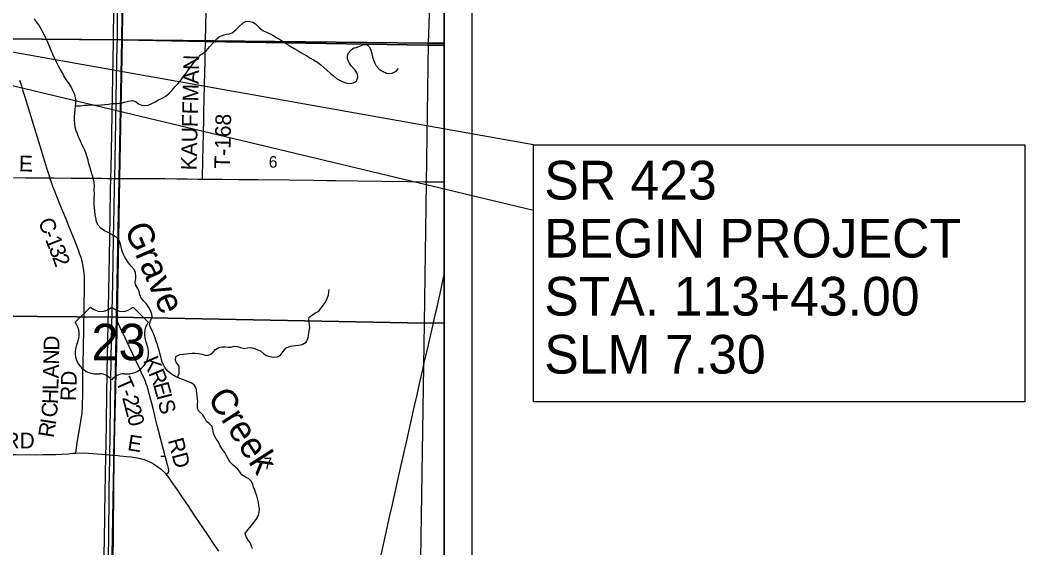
# Model space of a CAD drawing. Extents: x -9.1 to 34, y -3.1 to 22.
# Drawn here: x 7.865 to 11.501, y 15.91 to 17.82 of the extents above; entities that cross this region are included whole.
import ezdxf

# ---------------------------------------------------------------- set-up
doc = ezdxf.new("R2010")
doc.units = 0
for name, color, linetype in [('GM_X_County_Road', 7, 'Continuous'), ('GM_X_County_Road_Text', 7, 'Continuous'), ('GM_X_Minor_River', 7, 'Continuous'), ('GM_X_Minor_River_Text', 7, 'Continuous'), ('GM_X_Section', 7, 'Continuous'), ('GM_X_Section_Text', 7, 'Continuous'), ('GM_X_State_Route', 7, 'Continuous'), ('GM_X_Township', 7, 'Continuous'), ('GM_X_Township_Road', 7, 'Continuous'), ('GM_X_Township_Road_Text', 7, 'Continuous'), ('GM_X_US_Location', 7, 'Continuous'), ('GM_X_US_Route', 7, 'Continuous'), ('GM_X_US_Shield', 7, 'Continuous'), ('SH_Data', 7, 'Continuous'), ('SH_Text', 7, 'Continuous')]:
    doc.layers.add(name, color=color, linetype=linetype)

msp = doc.modelspace()

# ---------------------------------------------------------------- linework, layer by layer
at = {"layer": 'GM_X_County_Road'}
for points in [[(7.5906, 17.2523), (7.6358, 17.2517), (7.6699, 17.2515), (7.7072, 17.2509), (7.7694, 17.2501), (7.8315, 17.2497), (7.8844, 17.2494), (7.934, 17.2486), (7.9588, 17.2487), (7.9721, 17.2488)], [(8.0664, 16.2531), (8.0686, 16.2702), (8.0733, 16.2983), (8.0779, 16.3249), (8.0824, 16.3524), (8.0864, 16.3771), (8.088, 16.3894), (8.0891, 16.4018), (8.0902, 16.4173), (8.091, 16.4359), (8.0915, 16.4577), (8.0921, 16.5106), (8.0926, 16.5417), (8.0931, 16.5728), (8.0952, 16.7004), (8.0966, 16.7782), (8.098, 16.8591), (8.0981, 16.8777), (8.0977, 16.8933), (8.0971, 16.9025), (8.0962, 16.9118), (8.0949, 16.921), (8.0926, 16.9332), (8.0906, 16.9423), (8.0883, 16.9513), (8.0857, 16.9602), (8.0817, 16.972), (8.0763, 16.9865), (8.0614, 17.0241), (8.0463, 17.0617), (8.0313, 17.0993), (8.0093, 17.1541), (7.9921, 17.1975), (7.9839, 17.2177), (7.9781, 17.2322), (7.9721, 17.2488)], [(7.2729, 16.2483), (7.2946, 16.248), (7.3288, 16.2479), (7.3785, 16.2474), (7.4159, 16.2473), (7.4438, 16.2471), (7.4967, 16.2468), (7.5433, 16.2469), (7.5806, 16.2471), (7.6148, 16.2473), (7.6459, 16.2472), (7.6894, 16.2473), (7.7453, 16.2476), (7.7764, 16.2474), (7.8199, 16.2477), (7.851, 16.2477), (7.9224, 16.2469), (7.9473, 16.2474), (7.9655, 16.2476)], [(7.9655, 16.2476), (7.9663, 16.2476), (7.994, 16.2481), (8.0403, 16.2507), (8.056, 16.252), (8.0664, 16.2531)], [(8.0664, 16.2531), (8.0968, 16.2533), (8.1128, 16.2525), (8.16, 16.2491), (8.1754, 16.2477), (8.1799, 16.2472)], [(8.1799, 16.2472), (8.1896, 16.2464), (8.1979, 16.2456), (8.2067, 16.2448)], [(8.2067, 16.2448), (8.2187, 16.2437)], [(8.2187, 16.2437), (8.2257, 16.2431), (8.2504, 16.2407), (8.267, 16.239), (8.2811, 16.237), (8.2902, 16.2355), (8.2993, 16.2335), (8.3082, 16.2312), (8.3141, 16.2293), (8.3227, 16.2261), (8.3312, 16.2224), (8.3396, 16.2184), (8.3477, 16.2139), (8.3555, 16.209), (8.3631, 16.2037), (8.3704, 16.1981), (8.3751, 16.1941), (8.3842, 16.1857), (8.3888, 16.1814), (8.3939, 16.176)], [(8.4316, 16.1231), (8.4237, 16.1348), (8.4131, 16.1502), (8.404, 16.1628), (8.3939, 16.176)], [(8.5838, 15.8975), (8.565, 15.9259), (8.5441, 15.9569), (8.5285, 15.9802), (8.4954, 16.0292), (8.4727, 16.0627), (8.4482, 16.0988), (8.4316, 16.1231)]]:
    msp.add_lwpolyline(points, dxfattribs=at)
at = {"layer": 'GM_X_Minor_River'}
for points in [[(8.2332, 16.9877), (8.2306, 16.9994), (8.228, 17.0093), (8.2235, 17.0222), (8.2137, 17.0325), (8.2035, 17.0401), (8.1925, 17.0462), (8.1808, 17.0519), (8.1702, 17.0573), (8.1566, 17.0668), (8.146, 17.0786), (8.1415, 17.0903), (8.1385, 17.1036), (8.1371, 17.115), (8.1352, 17.1298), (8.1337, 17.14), (8.133, 17.1529), (8.1331, 17.1643), (8.1335, 17.1745), (8.1339, 17.1897), (8.1336, 17.206), (8.1337, 17.2192), (8.1326, 17.2314), (8.1307, 17.2424), (8.1277, 17.2538), (8.1247, 17.2636), (8.1217, 17.2735), (8.1169, 17.2891), (8.1142, 17.2997), (8.1109, 17.3122), (8.1071, 17.324), (8.1026, 17.3388), (8.0989, 17.349), (8.0933, 17.3608), (8.0876, 17.3729), (8.0812, 17.387), (8.0763, 17.3969), (8.0722, 17.4075), (8.0677, 17.4189), (8.064, 17.4318), (8.0625, 17.4443), (8.0614, 17.4568), (8.0614, 17.4689), (8.0626, 17.4829), (8.0638, 17.4962), (8.0654, 17.5083), (8.0662, 17.5193), (8.0666, 17.5307), (8.0644, 17.5455), (8.0606, 17.5554), (8.055, 17.5667), (8.0497, 17.5785), (8.0426, 17.5903), (8.0335, 17.6025), (8.0237, 17.6184), (8.0181, 17.6283), (8.0102, 17.6423), (8.0041, 17.6534), (7.997, 17.6674), (7.9902, 17.68), (7.9834, 17.6948), (7.9801, 17.705), (7.9752, 17.7156), (7.9639, 17.7422), (7.9583, 17.7536), (7.9519, 17.7669), (7.9462, 17.7779), (7.9387, 17.792), (7.9323, 17.8022), (7.9247, 17.8136), (7.9168, 17.8246)], [(8.0655, 17.5095), (8.0836, 17.5098), (8.0965, 17.512), (8.1071, 17.5123), (8.1204, 17.5131), (8.131, 17.5126), (8.1438, 17.5122), (8.1586, 17.5125), (8.1852, 17.5151), (8.1966, 17.5177), (8.2068, 17.518), (8.2174, 17.5176), (8.2303, 17.5191), (8.2432, 17.5225), (8.2572, 17.5262), (8.2713, 17.5284), (8.283, 17.5246), (8.2936, 17.5166), (8.3053, 17.5112), (8.3163, 17.5104), (8.3284, 17.5115), (8.3421, 17.5175), (8.3539, 17.5243), (8.3664, 17.5315), (8.379, 17.5371), (8.3919, 17.5446), (8.4025, 17.5529), (8.4147, 17.5665), (8.4265, 17.5794), (8.4364, 17.5907), (8.4474, 17.6036), (8.4554, 17.6141), (8.4665, 17.627), (8.4749, 17.6398), (8.4836, 17.6523), (8.4958, 17.669), (8.5065, 17.6818), (8.5175, 17.6939), (8.5282, 17.7014), (8.5396, 17.7097), (8.5498, 17.7226), (8.5635, 17.7373), (8.5769, 17.7513), (8.5867, 17.7603), (8.5993, 17.7656), (8.6122, 17.769), (8.622, 17.7701), (8.633, 17.7738), (8.6467, 17.7855), (8.6593, 17.798), (8.6726, 17.8093), (8.6836, 17.8153), (8.6969, 17.8145), (8.7071, 17.8126), (8.7173, 17.8057), (8.7305, 17.7928), (8.743, 17.7814), (8.7589, 17.7752), (8.7725, 17.7687), (8.7835, 17.763), (8.7967, 17.7546), (8.8069, 17.7478), (8.8202, 17.739), (8.8311, 17.7325), (8.8428, 17.7249), (8.8565, 17.7169), (8.8674, 17.7104), (8.878, 17.7039), (8.889, 17.6971), (8.9022, 17.6898), (8.9136, 17.6833), (8.9264, 17.6761), (8.9412, 17.6669), (8.9537, 17.6578), (8.9646, 17.6483), (8.9752, 17.6387), (8.9888, 17.6266), (8.999, 17.6178), (9.01, 17.6079), (9.0255, 17.5995), (9.0368, 17.5949), (9.0474, 17.5915), (9.0592, 17.5899), (9.0717, 17.5925), (9.0819, 17.5982), (9.0869, 17.6133), (9.0854, 17.6251), (9.0779, 17.6387), (9.0636, 17.6543), (9.0541, 17.6676), (9.05, 17.6794), (9.0497, 17.6904), (9.0539, 17.7006), (9.0627, 17.7123), (9.0725, 17.7191), (9.082, 17.721), (9.0972, 17.7262), (9.1078, 17.7307), (9.1196, 17.7307), (9.1294, 17.7212), (9.1343, 17.7105)], [(9.1343, 17.7105), (9.1376, 17.6973), (9.1403, 17.6863), (9.1433, 17.676), (9.1489, 17.6635), (9.1538, 17.654), (9.1647, 17.6418), (9.1749, 17.6346), (9.1905, 17.6281), (9.2007, 17.6265), (9.2113, 17.6276), (9.2261, 17.6348), (9.2349, 17.6446)], [(8.7063, 15.9061), (8.7029, 15.9156), (8.6984, 15.9266), (8.692, 15.9365), (8.683, 15.9494), (8.68, 15.9623), (8.6895, 15.9755), (8.7021, 15.9903), (8.7105, 16.0016), (8.7185, 16.0118), (8.7253, 16.0224), (8.7295, 16.0334), (8.7311, 16.0501), (8.7293, 16.0641), (8.7278, 16.0739), (8.7252, 16.0842), (8.7211, 16.0978), (8.7181, 16.1077), (8.7147, 16.1187), (8.7098, 16.1297), (8.7068, 16.1396), (8.7027, 16.1502), (8.6929, 16.1601), (8.6804, 16.1654), (8.6672, 16.1746), (8.6604, 16.1845), (8.6528, 16.1947), (8.6373, 16.2081), (8.6241, 16.2217), (8.6185, 16.2316), (8.6117, 16.2434), (8.6061, 16.2544), (8.5978, 16.2654), (8.5895, 16.2791), (8.5812, 16.2943), (8.574, 16.3049), (8.5684, 16.3148), (8.565, 16.3251), (8.562, 16.3376), (8.5587, 16.3497), (8.5492, 16.36), (8.539, 16.3676), (8.5338, 16.3797), (8.5259, 16.3911), (8.5119, 16.4041), (8.507, 16.4143), (8.5074, 16.4287), (8.5086, 16.4393), (8.5071, 16.4496), (8.5053, 16.4591), (8.5049, 16.4701), (8.5027, 16.4875), (8.4944, 16.5004), (8.4838, 16.5069), (8.4687, 16.5134), (8.4558, 16.5184), (8.443, 16.523), (8.4271, 16.5295), (8.4123, 16.5386), (8.3991, 16.5497), (8.3882, 16.5626), (8.3825, 16.5747), (8.378, 16.5854), (8.3743, 16.6024), (8.3709, 16.6142), (8.3679, 16.6252), (8.3649, 16.6354), (8.3619, 16.6453), (8.3574, 16.6571), (8.3533, 16.67), (8.3484, 16.6825), (8.3424, 16.6962), (8.3357, 16.7098), (8.333, 16.7193), (8.3373, 16.7314), (8.343, 16.7454), (8.3419, 16.7561), (8.3374, 16.7686), (8.331, 16.7796), (8.3219, 16.7933), (8.3121, 16.8032), (8.3019, 16.8161), (8.2986, 16.8256), (8.2963, 16.837), (8.2915, 16.8483), (8.2832, 16.862), (8.2817, 16.8738), (8.2833, 16.8836), (8.284, 16.8942), (8.2822, 16.9067), (8.2777, 16.9174), (8.2675, 16.9292), (8.2577, 16.9417), (8.2505, 16.9516), (8.243, 16.9641), (8.2385, 16.974), (8.2332, 16.9877)], [(8.4346, 16.5264), (8.4404, 16.5408), (8.4412, 16.5541), (8.4401, 16.5669), (8.4307, 16.5799), (8.4269, 16.5894), (8.4285, 16.6019), (8.4425, 16.609), (8.4551, 16.6109), (8.477, 16.613), (8.4869, 16.6141), (8.4983, 16.6141), (8.5115, 16.6133), (8.5244, 16.6106), (8.5388, 16.606), (8.5525, 16.6094), (8.5631, 16.6184), (8.5726, 16.6271), (8.5844, 16.6346), (8.5965, 16.6369), (8.606, 16.6372), (8.6178, 16.6364), (8.6284, 16.6364), (8.6394, 16.6397), (8.6515, 16.6386), (8.6629, 16.6343), (8.6769, 16.6316), (8.6882, 16.6339), (8.6989, 16.635), (8.7106, 16.6327), (8.7208, 16.6288), (8.736, 16.6219), (8.7473, 16.6124), (8.7571, 16.6056), (8.7692, 16.6021), (8.7833, 16.5998), (8.7961, 16.6009), (8.8056, 16.6065), (8.8175, 16.6205), (8.8262, 16.633), (8.8418, 16.6398), (8.8513, 16.6412), (8.8611, 16.6427), (8.874, 16.6438), (8.8858, 16.646), (8.9002, 16.6536), (8.9071, 16.6698), (8.909, 16.6801), (8.9114, 16.6937), (8.9133, 16.7062), (8.9122, 16.7164), (8.9104, 16.735), (8.9112, 16.7445), (8.9241, 16.7547), (8.9336, 16.7599), (8.9457, 16.7663), (8.9633, 16.789), (8.9701, 16.7988), (8.9762, 16.8125), (8.9805, 16.825), (8.9828, 16.8356), (8.9836, 16.845)]]:
    msp.add_lwpolyline(points, dxfattribs=at)
at = {"layer": 'GM_X_Section'}
for p, q in [((9.4, 17.736), (9.4, 18.7507)), ((9.4, 16.7243), (9.4, 17.736)), ((9.4, 15.7158), (9.4, 16.7243))]:
    msp.add_line(p, q, dxfattribs=at)
for points in [[(7.2285, 18.7534), (8.2465, 18.7547), (8.2334, 17.7485), (7.2227, 17.7567)], [(9.3766, 18.7507), (9.3419, 17.736), (8.2334, 17.7485), (8.2465, 18.7547)], [(8.2334, 17.7485), (8.2139, 16.745), (7.2066, 16.7532), (7.2227, 17.7567)], [(9.3419, 17.736), (9.3273, 16.7234), (8.2139, 16.745), (8.2334, 17.7485)], [(7.2066, 16.7532), (8.2139, 16.745), (8.1957, 15.7506), (7.6939, 15.7344), (7.1977, 15.7504)], [(8.2139, 16.745), (9.3273, 16.7234), (9.3112, 15.7153), (8.1958, 15.7211), (8.1957, 15.7506)]]:
    msp.add_lwpolyline(points, close=True, dxfattribs=at)
for points in [[(9.4, 18.7507), (9.3766, 18.7507), (9.3419, 17.736), (9.4, 17.736)], [(9.4, 17.736), (9.3419, 17.736), (9.3273, 16.7234), (9.4, 16.7243)], [(9.4, 16.7243), (9.3273, 16.7234), (9.3112, 15.7153), (9.4, 15.7158)]]:
    msp.add_lwpolyline(points, dxfattribs=at)
at = {"layer": 'GM_X_State_Route'}
for points in [[(7.8634, 17.6024), (7.8698, 17.5817), (7.8742, 17.5669), (7.8795, 17.5491), (7.8841, 17.5343), (7.8942, 17.5017), (7.9169, 17.4275), (7.9358, 17.3651), (7.9496, 17.3206), (7.9607, 17.285), (7.9721, 17.2488)], [(7.9721, 17.2488), (7.9884, 17.2487), (8.0496, 17.2477), (8.1309, 17.2473)], [(8.1309, 17.2473), (8.1614, 17.2472), (8.1819, 17.2469)], [(8.1819, 17.2469), (8.1863, 17.2469), (8.1879, 17.2469)], [(8.1879, 17.2469), (8.1934, 17.2469), (8.2049, 17.2469), (8.2074, 17.2469), (8.2239, 17.2469), (8.2266, 17.247), (8.2608, 17.2465), (8.3198, 17.2464), (8.3482, 17.2464)], [(8.3482, 17.2464), (8.3882, 17.2463), (8.4317, 17.2456), (8.469, 17.245), (8.5093, 17.2445), (8.5246, 17.2443), (8.5963, 17.2434), (8.6554, 17.2431), (8.6926, 17.2426), (8.7268, 17.2425), (8.8387, 17.241), (8.9256, 17.2401), (8.9754, 17.2393), (9.0064, 17.2388), (9.0872, 17.2379), (9.1742, 17.2366), (9.2674, 17.2353), (9.3295, 17.2348), (9.3668, 17.2343), (9.4, 17.2341)], [(9.1609, 15.8359), (9.1777, 15.9117), (9.1871, 15.9543), (9.2032, 16.027), (9.2121, 16.0664), (9.2331, 16.1606), (9.244, 16.2089), (9.2535, 16.2515), (9.2619, 16.2881), (9.2787, 16.363), (9.2925, 16.4243), (9.3017, 16.4638), (9.3106, 16.5031), (9.3222, 16.5547), (9.329, 16.585), (9.3389, 16.6274), (9.3477, 16.6668), (9.3595, 16.7184), (9.3684, 16.7577), (9.3739, 16.7811), (9.3788, 16.8033), (9.3849, 16.8306), (9.3963, 16.8822), (9.4, 16.8981)]]:
    msp.add_lwpolyline(points, dxfattribs=at)
at = {"layer": 'GM_X_Township'}
for points in [[(8.2717, 20.9), (8.2689, 20.7443), (8.2697, 20.6456), (8.2583, 19.8928), (8.2535, 19.4485), (8.2445, 18.5434), (8.2345, 17.7477), (8.5348, 17.7425), (9.3398, 17.7284), (9.4, 17.7292)], [(9.4, 17.7292), (9.4, 20.9), (8.2717, 20.9)], [(8.1877, 14.1), (8.1894, 14.7043), (8.1946, 15.2275), (8.1995, 15.7138), (8.204, 16.2447), (8.216, 16.7397), (8.2253, 17.2473), (8.2345, 17.7477), (8.2105, 17.7473), (7.8204, 17.7504), (7.686, 17.7514)], [(9.4, 17.7292), (9.3398, 17.7284), (8.5348, 17.7425), (8.2345, 17.7477), (8.2253, 17.2473), (8.216, 16.7397), (8.204, 16.2447), (8.1995, 15.7138), (8.1946, 15.2275), (8.1894, 14.7043), (8.1877, 14.1)], [(8.1877, 14.1), (9.4, 14.1), (9.4, 17.7292)]]:
    msp.add_lwpolyline(points, dxfattribs=at)
at = {"layer": 'GM_X_Township_Road'}
for points in [[(8.536, 17.7468), (8.5379, 17.8502), (8.5398, 17.931), (8.5409, 17.99), (8.5418, 18.0304), (8.5424, 18.0739), (8.5429, 18.1143), (8.5442, 18.187), (8.5451, 18.2375), (8.5452, 18.2542), (8.5457, 18.2741), (8.546, 18.2835), (8.5462, 18.292), (8.5464, 18.2978), (8.5466, 18.3052), (8.5468, 18.3128), (8.5469, 18.321), (8.5472, 18.3325), (8.5474, 18.3486), (8.5476, 18.3534), (8.5477, 18.3572), (8.5481, 18.3641), (8.5485, 18.3699)], [(8.5341, 17.6495), (8.5342, 17.6514), (8.5353, 17.7073), (8.5359, 17.7384), (8.536, 17.7468)], [(8.5246, 17.2443), (8.5247, 17.2503), (8.5262, 17.3127), (8.5282, 17.4093), (8.5294, 17.4592), (8.53, 17.4873), (8.531, 17.5341), (8.5322, 17.584), (8.5336, 17.632), (8.5341, 17.6495)], [(8.3905, 16.2412), (8.388, 16.2508), (8.3747, 16.302), (8.3661, 16.3351), (8.3616, 16.3532), (8.3555, 16.3773), (8.3485, 16.4044), (8.34, 16.4376), (8.3322, 16.4677), (8.3281, 16.4827), (8.3246, 16.4946), (8.3216, 16.5035), (8.3183, 16.5122), (8.3134, 16.5236), (8.307, 16.5378), (8.2979, 16.5576), (8.2849, 16.5856), (8.2592, 16.6391), (8.2449, 16.67), (8.2261, 16.7095), (8.217, 16.7293)], [(8.3737, 16.2412), (8.3867, 16.2412), (8.3905, 16.2412)], [(8.3939, 16.176), (8.4007, 16.1818), (8.4016, 16.183), (8.4023, 16.1844), (8.4031, 16.1874), (8.4033, 16.1905), (8.4029, 16.1936), (8.4021, 16.1966), (8.4004, 16.2026), (8.3999, 16.2056), (8.395, 16.2237), (8.3905, 16.2412)]]:
    msp.add_lwpolyline(points, dxfattribs=at)
at = {"layer": 'GM_X_US_Route'}
for points in [[(8.2072, 17.2359), (8.2074, 17.2469), (8.2085, 17.3114), (8.2114, 17.4543), (8.2143, 17.6096), (8.2166, 17.7277), (8.217, 17.7511), (8.2176, 17.8023), (8.2192, 17.939)], [(8.1663, 15.6793), (8.1707, 15.9589), (8.1712, 16.0042), (8.1716, 16.0352), (8.1723, 16.1081), (8.1736, 16.1733), (8.1754, 16.2477), (8.1761, 16.2789), (8.1805, 16.5492), (8.1835, 16.717), (8.1858, 16.8382), (8.1892, 17.0308), (8.191, 17.1147), (8.1925, 17.2047), (8.1934, 17.2469), (8.1943, 17.2824), (8.1965, 17.4098), (8.199, 17.5465), (8.2027, 17.7422), (8.2028, 17.7513), (8.204, 17.8603)], [(8.1702, 14.1), (8.1702, 14.1577), (8.1714, 14.4374), (8.1719, 14.6176), (8.1731, 14.8289), (8.1752, 15.0526), (8.1767, 15.2307), (8.177, 15.267), (8.1793, 15.4745), (8.1799, 15.5311), (8.1856, 15.9568), (8.1871, 16.0997), (8.1876, 16.1265), (8.1895, 16.2302), (8.1896, 16.2464), (8.1909, 16.3141), (8.1927, 16.4415), (8.1961, 16.6621), (8.2, 16.8672), (8.2034, 17.0318), (8.2052, 17.1374), (8.2068, 17.2151), (8.2072, 17.2359)]]:
    msp.add_lwpolyline(points, dxfattribs=at)
at = {"layer": 'GM_X_US_Shield'}
for p, q in [((8.1198, 16.7811), (8.0648, 16.7262)), ((8.3285, 16.7262), (8.2736, 16.7811)), ((8.1417, 16.5394), (8.1527, 16.5394)), ((8.2406, 16.5394), (8.2516, 16.5394))]:
    msp.add_line(p, q, dxfattribs=at)
for centre, radius, start, end in [((8.1582, 16.8204), 0.0549, 225.573, 314.427), ((8.2351, 16.8204), 0.0549, 225.573, 314.427), ((8.0018, 16.6821), 0.0769, 334.5471, 35.0009), ((8.3915, 16.6821), 0.0769, 144.9991, 205.4529), ((8.1409, 16.6163), 0.0769, 154.8319, 270.6383), ((8.2525, 16.6163), 0.0769, 269.3617, 25.1681), ((8.1527, 16.4845), 0.0549, 36.8699, 90), ((8.2406, 16.4845), 0.0549, 90, 143.1301)]:
    msp.add_arc(centre, radius, start, end, dxfattribs=at)
at = {"layer": 'SH_Data'}
for p, q in [((9.5, 21), (9.5, 14)), ((9.4, 20.9), (9.4, 14.1))]:
    msp.add_line(p, q, dxfattribs=at)
at = {"layer": 'SH_Text'}
for points in [[(9.7227, 17.3677), (5.8733, 18.0531), (9.7227, 17.1316)], [(9.7227, 17.3677), (11.5012, 17.3677), (11.5012, 16.4383), (9.7227, 16.4383)]]:
    msp.add_lwpolyline(points, close=True, dxfattribs=at)

# ---------------------------------------------------------------- texts
at = {"layer": 'GM_X_County_Road_Text'}
for s, height, rotation, p in [('E', 0.0568, 358.8923, (7.8601, 17.2724)), ('C', 0.0568, 291.6246, (7.9291, 17.0912)), ('-', 0.0568, 291.6159, (7.9463, 17.0478)), ('1', 0.0568, 291.5714, (7.9549, 17.0261)), ('3', 0.0568, 291.41, (7.9677, 16.9936)), ('2', 0.0568, 290.0694, (7.9804, 16.9614)), ('D', 0.0568, 88.7723, (8.0065, 16.6227)), ('N', 0.0568, 88.7723, (8.0054, 16.5727)), ('A', 0.0568, 88.7723, (8.0043, 16.5228)), ('RD', 0.05682, 88.5116, (8.0676, 16.4405)), ('L', 0.0568, 88.7791, (8.0034, 16.4803)), ('H', 0.0568, 87.9339, (8.0016, 16.4294)), ('C', 0.0568, 85.5794, (7.9978, 16.3803)), ('I', 0.0568, 80.8824, (7.9935, 16.3522)), ('RD', 0.05682, 0, (7.8083, 16.2699)), ('R', 0.0568, 80.6461, (7.9859, 16.3059)), ('E', 0.0568, 350.9456, (8.251, 16.2639))]:
    msp.add_text(s, height=height, rotation=rotation, dxfattribs=at).set_placement(p)
at = {"layer": 'GM_X_Minor_River_Text'}
for s, height, rotation, p in [('Grave', 0.09471, 293.3298, (8.2409, 17.0647)), ('Creek', 0.0947, 302.8291, (8.5404, 16.4525))]:
    msp.add_text(s, height=height, rotation=rotation, dxfattribs=at).set_placement(p)
at = {"layer": 'GM_X_Section_Text'}
for s, p in [('6', (8.765, 17.2856)), ('7', (8.7458, 16.194))]:
    msp.add_text(s, height=0.0419, rotation=0, dxfattribs=at).set_placement(p)
at = {"layer": 'GM_X_Township_Road_Text'}
for s, height, rotation, p in [('KAUFFMAN', 0.05682, 88.6577, (8.5035, 17.2755)), ('T-168', 0.05682, 88.5994, (8.6244, 17.2814)), ('K', 0.0568, 293.6965, (8.3088, 16.5883)), ('R', 0.0568, 292.2305, (8.3287, 16.5428)), ('T', 0.0568, 293.5931, (8.2098, 16.5126)), ('E', 0.0568, 285.5322, (8.3458, 16.5013)), ('-', 0.0568, 289.2175, (8.2264, 16.4748)), ('2', 0.0568, 284.7595, (8.2338, 16.4538)), ('I', 0.0568, 284.6705, (8.3572, 16.4606)), ('S', 0.0568, 284.6263, (8.3631, 16.438)), ('2', 0.0568, 284.555, (8.2427, 16.42)), ('0', 0.0568, 284.5184, (8.2515, 16.3862)), ('RD', 0.05682, 284.8671, (8.3992, 16.2995))]:
    msp.add_text(s, height=height, rotation=rotation, dxfattribs=at).set_placement(p)
at = {"layer": 'GM_X_US_Location'}
for s in ['0', '/']:
    msp.add_text(s, height=0.000189, dxfattribs=at).set_placement((8.1966, 16.6538))
msp.add_text('23', height=0.000189, rotation=0, dxfattribs=at).set_placement((8.1575, 16.6145))
at = {"layer": 'GM_X_US_Shield'}
msp.add_text('23', height=0.13184, dxfattribs=at).set_placement((8.1233, 16.5889))
at = {"layer": 'SH_Text'}
for s, p in [('SR 423', (9.7617, 17.1704)), ('BEGIN PROJECT', (9.7617, 16.9604)), ('STA. 113+43.00', (9.7617, 16.7504)), ('SLM 7.30', (9.7617, 16.5404))]:
    msp.add_text(s, height=0.14, dxfattribs=at).set_placement(p)

doc.saveas('drawing.dxf')
